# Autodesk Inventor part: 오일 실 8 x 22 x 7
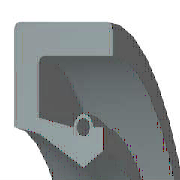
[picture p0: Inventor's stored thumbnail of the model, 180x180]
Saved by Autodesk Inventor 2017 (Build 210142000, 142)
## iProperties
IsCustomPart: 1
Created: 2012-02
Part Number: 오일 실 8 x 22 x 7
Material: 고무
Description: 오일-실
Document SubType Name: Modeling
Standard: KS B 2804
Designer: test
Standards Organization: KS
Language: ko-KR
Size Designation: S - 8 22 7
Categories: <MemberInstance><Categories><Category DisplayName="샤프트 부품" InternalName="7f7aeb1f-a693-4053-b835-cee3144e0d98" Mnemonic="SHFT"><Category DisplayName="실링" Intern
Density: 0.93 g/cm^3
Appearance: 고무 - 검은색 - 버전 1.1
Author: test
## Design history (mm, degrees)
revolve "본체" stored, may be unused: angle "d17" = 90 deg
revolve "스프링1" stored, may be unused: angle "d18" = 90 deg
body "Solid1"
sketch "스케치1"
  geometry: L1 (0, 11)-(7, 11); L2 (7, 11)-(7, 9.75); L3 (7, 9.75)-(1.75, 9.75); L4 (0, 11)-(0, 6.1); L5 (0, 6.1)-(1.75, 5.75); L6 (1.75, 5.75)-(4.9, 4); L7 (4.9, 4)-(0, 4); L8 (6.3, 4.875)-(6.3, 6.1); L9 (0, 0)-(9.586, 0) reference; L10 (4.9, 4)-(6.3, 4.875); L11 (0, 18)-(0, -3) reference; L12 (-1.917, 0)-(11.503, 0) reference; L13 (4.2, 6.1)-(1.75, 6.59); L14 (1.75, 6.59)-(1.75, 9.75); L15 (6.3, 6.1)-(5.6, 6.1); C1 r 0.455 at (4.9, 6.1); A1 r 0.7 centre (4.9, 6.1) between (5.6, 6.1) and (4.2, 6.1)
  constraints: 26 end point, 5 horizontal alignment, 4 perpendicular, 2 centre point, 2 collinear, 2 horizontal, 2 parallel, 2 point on circle, 2 point on line, 2 vertical alignment, 1 coincident
  dimensions: "d0" = 22 diameter of L1 L9 (= SD2); "d1" = 9.75 diameter of L8.start L9 (= ABDM); "d2" = 1.25 distance of L1.end L2.end (computed from SD); "d3" = 0.91 diameter of C1 (= SPDI); "d4" = 1.4 diameter of A1 (= SPDA); "d5" = 8 diameter of L6.end L9 (= NND); "d6" = 11.5 diameter of L5.end L9 (= TKDM); "d7" = 12.2 diameter of L4.end L9 (= HLDM); "d8" = 4.9 distance from line of C1.centre L4 (= SPDST); "d9" = 6.3 distance between parallel lines of L8 L4 (= SDI); "d10" = 7 distance between parallel lines of L2 L4 (= SWDT); "d12" = 1.75 distance between parallel lines of L14 L4 (= SD)
fillet "모깎기1" dims "d11" = 0.3 (= RR)
other parameters: "SD2" = 22 [user parameter; used in 1 equation term], "SWDT" = 7 [user parameter; used in 1 equation term], "RR" = 0.3 [user parameter; used in 1 equation term], "SD" = 1.75 [user parameter; used in 2 equation terms], "NND" = 8 [user parameter; used in 1 equation term], "SPDA" = 1.4 [user parameter; used in 1 equation term], "SPDI" = 0.91 [user parameter; used in 1 equation term], "TKDM" = 11.5 [user parameter; used in 1 equation term], "HLDM" = 12.2 [user parameter; used in 1 equation term], "ABDM" = 9.75 [user parameter; used in 1 equation term], "SDI" = 6.3 [user parameter; used in 1 equation term], "SPDST" = 4.9 [user parameter; used in 1 equation term], "d13" = 0, "d14" = 0, "d15" = 0, "LAB" = 0.35 [user parameter]
